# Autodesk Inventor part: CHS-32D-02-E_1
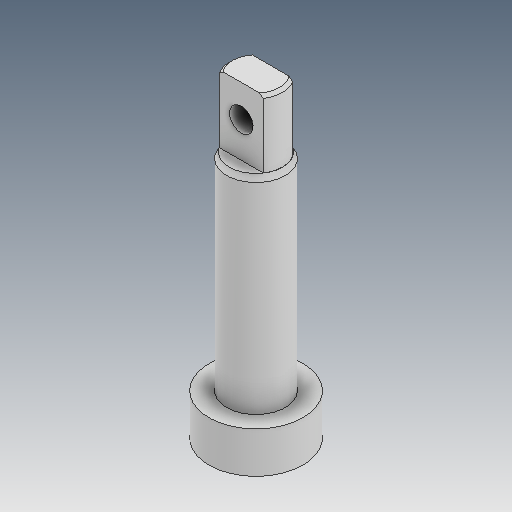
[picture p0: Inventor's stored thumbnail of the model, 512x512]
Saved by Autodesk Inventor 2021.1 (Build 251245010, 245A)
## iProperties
Created: 2021-05
Part Number: CHS-32D-02-E_1
Material: Ogólny
Document SubType Name: Modeling
Designer: user
Density: 1 g/cm^3
Appearance: Domyślna
Author: user
Revision Number: ÈÎºÎ
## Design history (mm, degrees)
feature "ÊäÈë1"
feature "ÊäÈë2"
node "Bryła1"
node "Bryła2"
